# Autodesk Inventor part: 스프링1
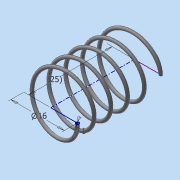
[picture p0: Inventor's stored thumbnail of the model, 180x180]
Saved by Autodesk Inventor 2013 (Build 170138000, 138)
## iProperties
Created: 2015-11
Part Number: 스프링1
Material: 일반
Document SubType Name: Modeling
Designer: dgall
Density: 1 g/cm^3
Author: dgall
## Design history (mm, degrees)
sketch "스케치1"
  geometry: L1 (8, 0)-(0, 0); L2 (0, 0)-(0, 16.67); L3 (0, 16.67)-(8, 16.67); C1 r 0.5 at (8, 0)
  constraints: 6 end point, 1 centre point, 1 coincident, 1 horizontal, 1 parallel, 1 perpendicular, 1 vertical alignment
  dimensions: "d5" = 16 diameter of L1.start L2; "d7" = 16.66987 distance of L1.end L2.end (derived); "d8" = 1 diameter of C1
feature "코일1" pitch "d9" = 10; turns "d11" = 5; dims "d10" = 16.66987 (= d7), "d12" = 0, angle "d13" = 90 deg, angle "d14" = 90 deg, "d15" = 0, "d16" = 0
sketch "스케치2"
  geometry: L1 (-10, 0)-(10, 0); L2 (10, 0)-(10, -5); L3 (10, -5)-(-10, -5); L4 (-10, -5)-(-10, 0); L5 (-10, 30)-(10, 30); L6 (10, 30)-(10, 25); L7 (10, 25)-(-10, 25); L8 (-10, 25)-(-10, 30); 4 further points
  constraints: 16 end point, 4 parallel, 3 midpoint, 2 horizontal, 2 perpendicular, 1 coincident, 1 vertical alignment
  dimensions: "d17" = 25 distance between parallel lines of L7 L1; "d18" = 5 distance of L7.end L5.start; "d19" = 5 distance of L3.end L1.start; "d20" = 20 distance of L2.end L3.end; "d21" = 20 distance of L5.start L5.end
extrude "돌출1" cut sketch "스케치2" stored distance "d22" = 30; taper "d23" = 0 deg
node "솔리드1"
